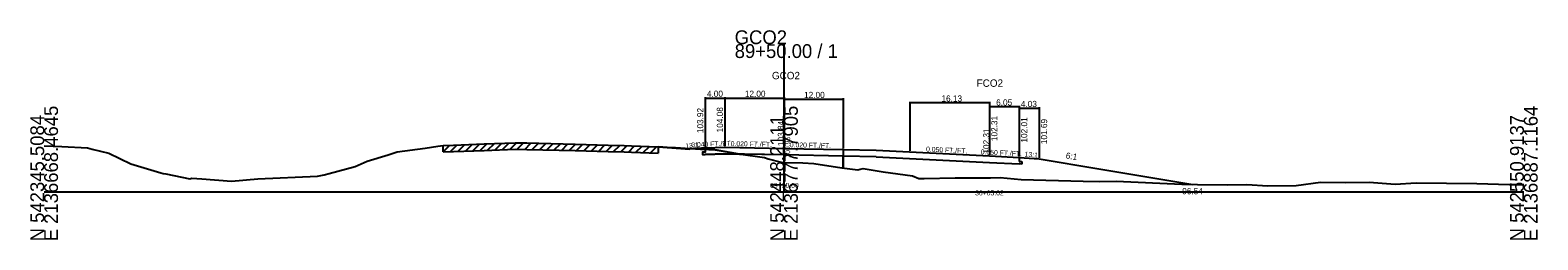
# Model space of a CAD drawing. Extents: x -14327 to 8886, y -10 to 39048.
# Drawn here: x 2997.2 to 3302.8, y 38990.3 to 39032.8 of the extents above; entities that cross this region are included whole.
import ezdxf

# ---------------------------------------------------------------- set-up
doc = ezdxf.new("R2010")
doc.units = 0
for name, color, linetype in [('Level 20', 7, 'Continuous'), ('Level 5', 7, 'Continuous'), ('Level 53', 7, 'Continuous'), ('Level 54', 7, 'Continuous'), ('Level 55', 7, 'Continuous'), ('Level 7', 7, 'Continuous'), ('RD_GPK_XS_Cell', 7, 'Continuous'), ('RD_XS_EwShp', 7, 'Continuous'), ('RD_XS_ExGround', 7, 'Continuous'), ('RD_XS_ExPaveRet', 7, 'Continuous'), ('RD_XS_Pave', 7, 'Continuous'), ('RD_XS_TX_Baseline', 7, 'Continuous'), ('RD_XS_TX_Elev_EX', 7, 'Continuous'), ('RD_XS_TX_Elev_PR', 7, 'Continuous'), ('RD_XS_TX_Station', 7, 'Continuous')]:
    doc.layers.add(name, color=color, linetype=linetype)

msp = doc.modelspace()

# ---------------------------------------------------------------- linework, layer by layer
at = {"layer": 'Level 20'}
for p, q in [((3175.5, 39018.27), (3175.5, 39008.32)), ((3191.63, 39018.07), (3175.5, 39018.07)), ((3191.63, 39018.27), (3191.63, 39007.51)), ((3191.63, 39017.46), (3191.63, 39007.51)), ((3197.68, 39017.26), (3191.63, 39017.26)), ((3197.68, 39017.46), (3197.68, 39007.21)), ((3197.68, 39017.16), (3197.68, 39007.21)), ((3197.68, 39016.96), (3201.71, 39016.96)), ((3201.71, 39017.16), (3201.71, 39006.89)), ((3162, 39008.6), (3168.68, 39008.47)), ((3168.68, 39008.47), (3191.63, 39007.31)), ((3168.68, 39007.13), (3162, 39007.27)), ((3168.68, 39007.13), (3191.63, 39005.98)), ((3191.63, 39007.31), (3197.68, 39007.01)), ((3191.63, 39005.98), (3197.68, 39005.68)), ((3197.68, 39007.01), (3197.68, 39006.18)), ((3197.68, 39007.01), (3201.71, 39006.69)), ((3197.68, 39006.18), (3198.19, 39006.15)), ((3198.19, 39005.65), (3197.68, 39005.68)), ((3198.19, 39006.15), (3198.19, 39005.65)), ((3201.71, 39006.69), (3213.81, 39004.69)), ((3213.81, 39004.69), (3232.87, 39001.54))]:
    msp.add_line(p, q, dxfattribs=at)
at = {"layer": 'Level 5'}
for p, q in [((3134, 39008.09), (3133.5, 39008.07)), ((3133.5, 39008.07), (3133.5, 39007.57)), ((3134, 39008.92), (3134, 39008.09)), ((3133.5, 39007.57), (3134, 39007.59)), ((3138, 39007.75), (3134, 39007.59)), ((3150, 39007.51), (3138, 39007.75)), ((3162, 39007.27), (3150, 39007.51))]:
    msp.add_line(p, q, dxfattribs=at)
at = {"layer": 'Level 54'}
for p, q in [((3134, 39019.23), (3134, 39009.12)), ((3134, 39019.07), (3134, 39009.12)), ((3134, 39019.03), (3138, 39019.03)), ((3138, 39019.23), (3138, 39009.28)), ((3138, 39019.03), (3150, 39019.03)), ((3150, 39019.23), (3150, 39009.04)), ((3150, 39018.99), (3150, 39009.04)), ((3150, 39018.79), (3162, 39018.79)), ((3162, 39018.99), (3162, 39008.8))]:
    msp.add_line(p, q, dxfattribs=at)
at = {"layer": 'Level 7'}
for p, q in [((3124.5, 39009.18), (3130.88, 39008.67)), ((3134, 39008.92), (3130.88, 39008.67)), ((3162, 39007.27), (3162, 39004.88))]:
    msp.add_line(p, q, dxfattribs=at)
at = {"layer": 'RD_GPK_XS_Cell'}
for p, q in [((3150, 39000), (3150, 39029.95)), ((3000, 39000), (3150, 39000)), ((3150, 39000), (3300, 39000))]:
    msp.add_line(p, q, dxfattribs=at)
at = {"layer": 'RD_XS_EwShp'}
for points in [[(3132.03, 39008.76), (3130.88, 39008.67), (3124.5, 39009.18), (3127.43, 39009.02), (3128.01, 39009), (3130.98, 39008.83)], [(3132.03, 39008.76), (3134, 39008.64), (3134, 39008.92)], [(3134, 39008.64), (3134, 39008.09), (3133.5, 39008.07), (3133.5, 39007.57), (3134, 39007.59), (3138, 39007.75), (3140.96, 39007.69), (3136.04, 39008.52)], [(3153.84, 39005.91), (3156.04, 39005.78), (3161.74, 39004.91), (3162, 39004.88), (3162, 39007.27), (3150, 39007.51), (3140.96, 39007.69), (3141.26, 39007.64), (3146.04, 39006.96), (3146.77, 39006.7), (3149.44, 39006.02), (3150.08, 39005.95)]]:
    msp.add_lwpolyline(points, close=True, dxfattribs=at)
at = {"layer": 'RD_XS_ExGround'}
for p, q in [((3000, 39009.37), (3003.61, 39009.22)), ((3003.61, 39009.22), (3008.78, 39008.95)), ((3008.78, 39008.95), (3009.76, 39008.69)), ((3009.76, 39008.69), (3013.13, 39007.84)), ((3069.77, 39007.56), (3071.55, 39008.11)), ((3071.55, 39008.11), (3077.25, 39008.91)), ((3077.25, 39008.91), (3079.82, 39009.27)), ((3079.82, 39009.27), (3080.9, 39009.42)), ((3080.9, 39009.42), (3082.99, 39009.5)), ((3082.99, 39009.5), (3089.19, 39009.74)), ((3089.19, 39009.74), (3095.52, 39009.98)), ((3095.52, 39009.98), (3097.88, 39009.93)), ((3097.88, 39009.93), (3107.65, 39009.71)), ((3107.65, 39009.71), (3114.35, 39009.51)), ((3114.35, 39009.51), (3117.59, 39009.42)), ((3117.59, 39009.42), (3119.1, 39009.38)), ((3119.1, 39009.38), (3124.5, 39009.18)), ((3124.5, 39009.18), (3127.43, 39009.02)), ((3127.43, 39009.02), (3128.01, 39009)), ((3128.01, 39009), (3130.98, 39008.83)), ((3130.98, 39008.83), (3136.04, 39008.52)), ((3136.04, 39008.52), (3141.26, 39007.64)), ((3013.13, 39007.84), (3017.54, 39005.68)), ((3017.54, 39005.68), (3023.68, 39003.9)), ((3057.81, 39003.78), (3063.06, 39005.19)), ((3063.06, 39005.19), (3065.48, 39006.25)), ((3065.48, 39006.25), (3069.77, 39007.56)), ((3141.26, 39007.64), (3146.04, 39006.96)), ((3146.04, 39006.96), (3146.77, 39006.7)), ((3146.77, 39006.7), (3149.44, 39006.02)), ((3149.44, 39006.02), (3150.08, 39005.95)), ((3150.08, 39005.95), (3153.84, 39005.91)), ((3153.84, 39005.91), (3156.04, 39005.78)), ((3156.04, 39005.78), (3161.74, 39004.91)), ((3023.68, 39003.9), (3024.12, 39003.77)), ((3024.12, 39003.77), (3024.68, 39003.66)), ((3024.68, 39003.66), (3029.54, 39002.68)), ((3029.54, 39002.68), (3029.94, 39002.82)), ((3029.94, 39002.82), (3031.96, 39002.68)), ((3031.96, 39002.68), (3037.95, 39002.22)), ((3037.95, 39002.22), (3043.29, 39002.65)), ((3043.29, 39002.65), (3055.39, 39003.23)), ((3055.39, 39003.23), (3056.77, 39003.49)), ((3056.77, 39003.49), (3057.81, 39003.78)), ((3161.74, 39004.91), (3164.97, 39004.46)), ((3164.97, 39004.46), (3165.42, 39004.6)), ((3165.42, 39004.6), (3166.05, 39004.75)), ((3166.05, 39004.75), (3170.08, 39004.08)), ((3170.08, 39004.08), (3176.05, 39003.24)), ((3176.05, 39003.24), (3177.31, 39002.73)), ((3177.31, 39002.73), (3178.42, 39002.72)), ((3178.42, 39002.72), (3184.73, 39002.87)), ((3184.73, 39002.87), (3191.9, 39002.89)), ((3191.9, 39002.89), (3193.81, 39002.93)), ((3193.81, 39002.93), (3198.1, 39002.56)), ((3198.1, 39002.56), (3210.63, 39002.21)), ((3210.63, 39002.21), (3213.92, 39002.13)), ((3213.92, 39002.13), (3217.33, 39002.22)), ((3217.33, 39002.22), (3230.66, 39001.59)), ((3253.86, 39001.29), (3258.78, 39001.97)), ((3258.78, 39001.97), (3263.87, 39001.94)), ((3263.87, 39001.94), (3268.67, 39002.01)), ((3268.67, 39002.01), (3273.88, 39001.59)), ((3230.66, 39001.59), (3233.84, 39001.52)), ((3233.84, 39001.52), (3239.91, 39001.45)), ((3239.91, 39001.45), (3243.85, 39001.5)), ((3243.85, 39001.5), (3248.09, 39001.27)), ((3248.09, 39001.27), (3253.86, 39001.29)), ((3273.88, 39001.59), (3278.14, 39001.85)), ((3278.14, 39001.85), (3290.44, 39001.71)), ((3290.44, 39001.71), (3297.12, 39001.52)), ((3297.12, 39001.52), (3300, 39001.53))]:
    msp.add_line(p, q, dxfattribs=at)
at = {"layer": 'RD_XS_ExPaveRet'}
for p, q in [((3080.9, 39008.12), (3082.26, 39009.47)), ((3080.9, 39008.12), (3080.9, 39009.42)), ((3080.9, 39008.12), (3082.99, 39008.2)), ((3082.4, 39008.18), (3083.76, 39009.53)), ((3082.99, 39008.2), (3089.19, 39008.44)), ((3083.91, 39008.24), (3085.26, 39009.59)), ((3085.41, 39008.3), (3086.76, 39009.65)), ((3086.91, 39008.35), (3088.26, 39009.71)), ((3088.41, 39008.41), (3089.76, 39009.76)), ((3089.19, 39008.44), (3095.52, 39008.68)), ((3089.91, 39008.47), (3091.27, 39009.82)), ((3091.41, 39008.53), (3092.77, 39009.88)), ((3092.92, 39008.58), (3094.27, 39009.93)), ((3094.42, 39008.64), (3095.76, 39009.98)), ((3095.52, 39008.68), (3097.88, 39008.63)), ((3095.92, 39008.67), (3097.19, 39009.94)), ((3097.42, 39008.64), (3098.7, 39009.91)), ((3097.88, 39008.63), (3107.65, 39008.41)), ((3098.92, 39008.61), (3100.2, 39009.88)), ((3100.43, 39008.57), (3101.7, 39009.84)), ((3101.93, 39008.54), (3103.2, 39009.81)), ((3103.43, 39008.51), (3104.7, 39009.78)), ((3104.93, 39008.47), (3106.2, 39009.74)), ((3106.43, 39008.44), (3107.71, 39009.71)), ((3107.65, 39008.41), (3114.35, 39008.21)), ((3107.93, 39008.4), (3109.2, 39009.67)), ((3109.44, 39008.36), (3110.7, 39009.62)), ((3110.94, 39008.31), (3112.2, 39009.58)), ((3112.44, 39008.27), (3113.7, 39009.53)), ((3113.94, 39008.22), (3115.21, 39009.49)), ((3114.35, 39008.21), (3117.59, 39008.12)), ((3115.44, 39008.18), (3116.71, 39009.45)), ((3116.95, 39008.14), (3118.21, 39009.4)), ((3117.59, 39008.12), (3119.1, 39008.08)), ((3118.45, 39008.1), (3119.71, 39009.35)), ((3119.1, 39008.08), (3124.5, 39007.88)), ((3119.95, 39008.05), (3121.21, 39009.3)), ((3121.45, 39007.99), (3122.71, 39009.25)), ((3122.95, 39007.94), (3124.21, 39009.19)), ((3124.5, 39009.18), (3124.5, 39007.88))]:
    msp.add_line(p, q, dxfattribs=at)
at = {"layer": 'RD_XS_Pave'}
for p, q in [((3134, 39008.92), (3138, 39009.08)), ((3138, 39009.08), (3150, 39008.84)), ((3150, 39008.84), (3162, 39008.6)), ((3162, 39008.6), (3162, 39007.27))]:
    msp.add_line(p, q, dxfattribs=at)

# ---------------------------------------------------------------- texts
at = {"layer": 'Level 20'}
for s, height, p in [('FCO2', 1.5, (3189.06, 39021.31)), ('16.13', 1.25, (3181.92, 39018.32)), ('6.05', 1.25, (3193.01, 39017.51)), ('4.03', 1.25, (3198.02, 39017.21)), ('36+05.02', 1, (3188.75, 38999.31)), ('96.54', 1.25, (3230.74, 38999.54))]:
    msp.add_text(s, height=height, dxfattribs=at).set_placement(p)
for s, height, rotation, p in [('102.31', 1.25, 90, (3193.27, 39010.31)), ('102.01', 1.25, 90, (3199.31, 39010.01)), ('101.69', 1.25, 90, (3203.35, 39009.69)), (' 102.31', 1.25, 90, (3191.63, 39007.31)), ('0.050 FT./FT.', 1, 357.1259, (3178.78, 39008.21)), ('0.050 FT./FT.', 1, 357.1258, (3189.87, 39007.65)), ('13:1', 1, 355.4629, (3198.76, 39007.18)), ('6:1', 1.25, 350.6127, (3207.06, 39006.82))]:
    msp.add_text(s, height=height, rotation=rotation, dxfattribs=at).set_placement(p)
at = {"layer": 'Level 53'}
for s, p in [('103.92', (3133.63, 39011.92)), ('104.08', (3137.62, 39012.08))]:
    msp.add_text(s, height=1.25, rotation=90, dxfattribs=at).set_placement(p)
at = {"layer": 'Level 54'}
for s, p in [('4.00', (3134.37, 39019.28)), ('12.00', (3142.07, 39019.28)), ('12.00', (3154.07, 39019.04))]:
    msp.add_text(s, height=1.25, dxfattribs=at).set_placement(p)
at = {"layer": 'Level 55'}
for s, rotation, p in [('13:1', 4.5739, (3130.03, 39008.85)), ('0.040 FT./FT.', 2.2906, (3131.22, 39009.06)), ('0.020 FT./FT.', 358.8542, (3139.18, 39009.31)), ('0.020 FT./FT.', 358.8542, (3151.18, 39009.07))]:
    msp.add_text(s, height=1, rotation=rotation, dxfattribs=at).set_placement(p)
at = {"layer": 'RD_GPK_XS_Cell'}
for s, p in [('GCO2', (3140, 39029.95)), ('89+50.00 / 1', (3140, 39027.15))]:
    msp.add_text(s, height=2.8, dxfattribs=at).set_placement(p)
for s, p in [('E 2136668.4645', (3002.8, 38990)), ('E 2136777.7905', (3152.8, 38990)), ('E 2136887.1164', (3302.8, 38990)), ('N 542345.5084', (3000, 38990)), ('N 542448.2111', (3150, 38990)), ('N 542550.9137', (3300, 38990))]:
    msp.add_text(s, height=2.8, rotation=90, dxfattribs=at).set_placement(p)
at = {"layer": 'RD_XS_TX_Baseline'}
msp.add_text('GCO2', height=1.5, dxfattribs=at).set_placement((3147.55, 39022.84))
at = {"layer": 'RD_XS_TX_Elev_EX'}
msp.add_text('100.95', height=1, rotation=90, dxfattribs=at).set_placement((3151.25, 39006.95))
at = {"layer": 'RD_XS_TX_Elev_PR'}
msp.add_text(' 103.84', height=1.25, rotation=90, dxfattribs=at).set_placement((3150, 39008.84))
at = {"layer": 'RD_XS_TX_Station'}
msp.add_text('89+50.00', height=1, dxfattribs=at).set_placement((3147.19, 39000.84))

doc.saveas('drawing.dxf')
